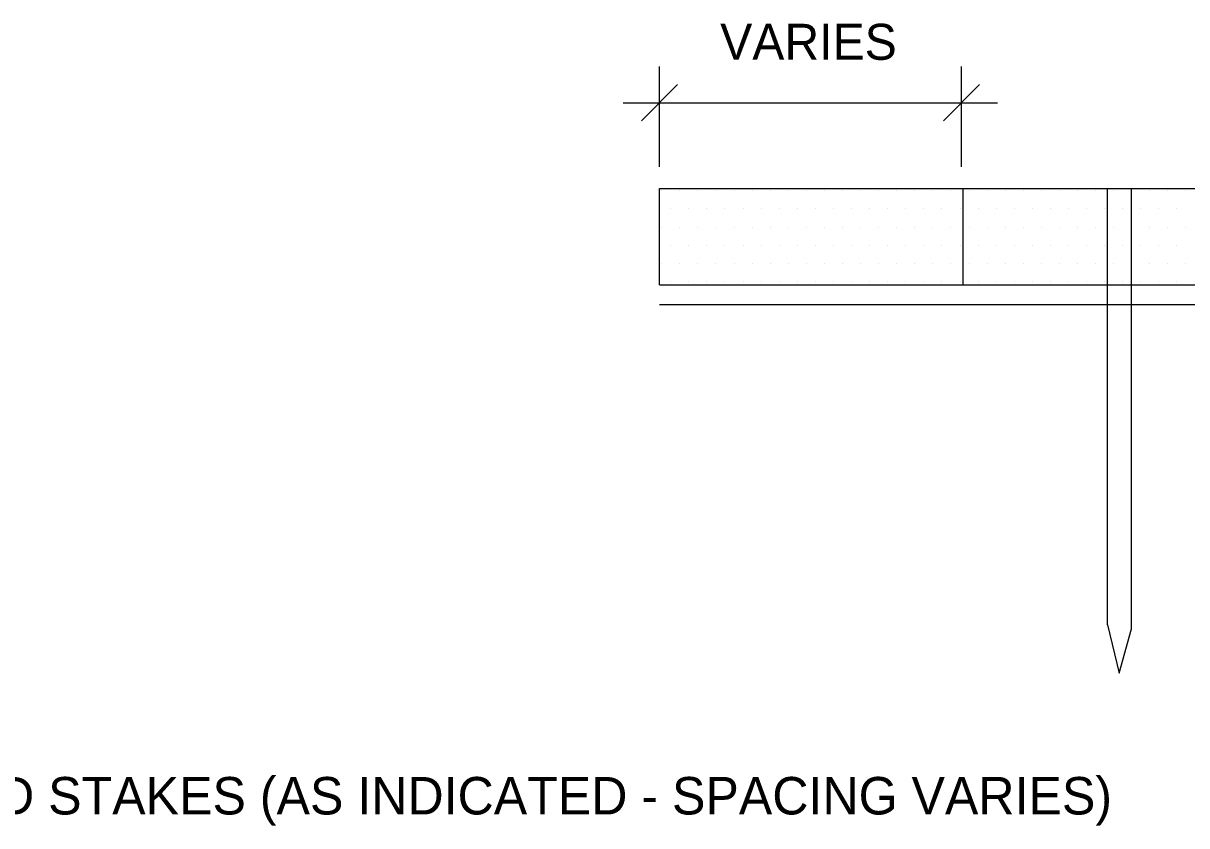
# Model space of a CAD drawing. Extents: x 638850 to 644908, y 297188 to 298900.
# Drawn here: x 641612.1 to 641700.1, y 297637.1 to 297697.8 of the extents above; entities that cross this region are included whole.
import ezdxf

# ---------------------------------------------------------------- set-up
doc = ezdxf.new("R2010")
doc.units = 0
for name, color, linetype in [('11', 7, 'Continuous'), ('3', 7, 'Continuous'), ('4', 7, 'Continuous'), ('5', 7, 'Continuous'), ('6', 7, 'Continuous'), ('7', 7, 'Continuous')]:
    doc.layers.add(name, color=color, linetype=linetype)

msp = doc.modelspace()

# ---------------------------------------------------------------- linework, layer by layer
at = {"layer": '11'}
for p, q in [((641660.41, 297685.127), (641660.41, 297685.127)), ((641661.777, 297685.127), (641661.777, 297685.127)), ((641663.143, 297685.127), (641663.143, 297685.127)), ((641664.51, 297685.127), (641664.51, 297685.127)), ((641665.877, 297685.127), (641665.877, 297685.127)), ((641667.244, 297685.127), (641667.244, 297685.127)), ((641668.611, 297685.127), (641668.611, 297685.127)), ((641669.978, 297685.127), (641669.978, 297685.127)), ((641671.345, 297685.127), (641671.345, 297685.127)), ((641672.712, 297685.127), (641672.712, 297685.127)), ((641674.078, 297685.127), (641674.078, 297685.127)), ((641675.445, 297685.127), (641675.445, 297685.127)), ((641676.812, 297685.127), (641676.812, 297685.127)), ((641678.179, 297685.127), (641678.179, 297685.127)), ((641679.546, 297685.127), (641679.546, 297685.127)), ((641680.913, 297685.127), (641680.913, 297685.127)), ((641682.28, 297685.127), (641682.28, 297685.127)), ((641683.647, 297685.127), (641683.647, 297685.127)), ((641685.013, 297685.127), (641685.013, 297685.127)), ((641686.38, 297685.127), (641686.38, 297685.127)), ((641687.747, 297685.127), (641687.747, 297685.127)), ((641689.114, 297685.127), (641689.114, 297685.127)), ((641690.481, 297685.127), (641690.481, 297685.127)), ((641691.848, 297685.127), (641691.848, 297685.127)), ((641693.215, 297685.127), (641693.215, 297685.127)), ((641694.582, 297685.127), (641694.582, 297685.127)), ((641695.948, 297685.127), (641695.948, 297685.127)), ((641697.315, 297685.127), (641697.315, 297685.127)), ((641698.682, 297685.127), (641698.682, 297685.127)), ((641700.049, 297685.127), (641700.049, 297685.127)), ((641661.094, 297683.76), (641661.094, 297683.76)), ((641662.459, 297683.76), (641662.459, 297683.76)), ((641663.828, 297683.76), (641663.828, 297683.76)), ((641665.193, 297683.76), (641665.193, 297683.76)), ((641666.562, 297683.76), (641666.562, 297683.76)), ((641667.926, 297683.76), (641667.926, 297683.76)), ((641669.295, 297683.76), (641669.295, 297683.76)), ((641670.66, 297683.76), (641670.66, 297683.76)), ((641672.029, 297683.76), (641672.029, 297683.76)), ((641673.394, 297683.76), (641673.394, 297683.76)), ((641674.763, 297683.76), (641674.763, 297683.76)), ((641676.128, 297683.76), (641676.128, 297683.76)), ((641677.497, 297683.76), (641677.497, 297683.76)), ((641678.861, 297683.76), (641678.861, 297683.76)), ((641680.23, 297683.76), (641680.23, 297683.76)), ((641681.595, 297683.76), (641681.595, 297683.76)), ((641682.964, 297683.76), (641682.964, 297683.76)), ((641684.329, 297683.76), (641684.329, 297683.76)), ((641685.698, 297683.76), (641685.698, 297683.76)), ((641687.063, 297683.76), (641687.063, 297683.76)), ((641688.432, 297683.76), (641688.432, 297683.76)), ((641689.796, 297683.76), (641689.796, 297683.76)), ((641691.165, 297683.76), (641691.165, 297683.76)), ((641692.53, 297683.76), (641692.53, 297683.76)), ((641693.899, 297683.76), (641693.899, 297683.76)), ((641695.264, 297683.76), (641695.264, 297683.76)), ((641696.633, 297683.76), (641696.633, 297683.76)), ((641697.998, 297683.76), (641697.998, 297683.76)), ((641699.367, 297683.76), (641699.367, 297683.76)), ((641660.41, 297682.393), (641660.41, 297682.393)), ((641661.777, 297682.393), (641661.777, 297682.393)), ((641663.143, 297682.393), (641663.143, 297682.393)), ((641664.51, 297682.393), (641664.51, 297682.393)), ((641665.877, 297682.393), (641665.877, 297682.393)), ((641667.244, 297682.393), (641667.244, 297682.393)), ((641668.611, 297682.393), (641668.611, 297682.393)), ((641669.978, 297682.393), (641669.978, 297682.393)), ((641671.345, 297682.393), (641671.345, 297682.393)), ((641672.712, 297682.393), (641672.712, 297682.393)), ((641674.078, 297682.393), (641674.078, 297682.393)), ((641675.445, 297682.393), (641675.445, 297682.393)), ((641676.812, 297682.393), (641676.812, 297682.393)), ((641678.179, 297682.393), (641678.179, 297682.393)), ((641679.546, 297682.393), (641679.546, 297682.393)), ((641680.913, 297682.393), (641680.913, 297682.393)), ((641682.28, 297682.393), (641682.28, 297682.393)), ((641683.647, 297682.393), (641683.647, 297682.393)), ((641685.013, 297682.393), (641685.013, 297682.393)), ((641686.38, 297682.393), (641686.38, 297682.393)), ((641687.747, 297682.393), (641687.747, 297682.393)), ((641689.114, 297682.393), (641689.114, 297682.393)), ((641690.481, 297682.393), (641690.481, 297682.393)), ((641691.848, 297682.393), (641691.848, 297682.393)), ((641693.215, 297682.393), (641693.215, 297682.393)), ((641694.582, 297682.393), (641694.582, 297682.393)), ((641695.948, 297682.393), (641695.948, 297682.393)), ((641697.315, 297682.393), (641697.315, 297682.393)), ((641698.682, 297682.393), (641698.682, 297682.393)), ((641700.049, 297682.393), (641700.049, 297682.393)), ((641661.094, 297681.026), (641661.094, 297681.026)), ((641662.459, 297681.026), (641662.459, 297681.026)), ((641663.828, 297681.026), (641663.828, 297681.026)), ((641665.193, 297681.026), (641665.193, 297681.026)), ((641666.562, 297681.026), (641666.562, 297681.026)), ((641667.926, 297681.026), (641667.926, 297681.026)), ((641669.295, 297681.026), (641669.295, 297681.026)), ((641670.66, 297681.026), (641670.66, 297681.026)), ((641672.029, 297681.026), (641672.029, 297681.026)), ((641673.394, 297681.026), (641673.394, 297681.026)), ((641674.763, 297681.026), (641674.763, 297681.026)), ((641676.128, 297681.026), (641676.128, 297681.026)), ((641677.497, 297681.026), (641677.497, 297681.026)), ((641678.861, 297681.026), (641678.861, 297681.026)), ((641680.23, 297681.026), (641680.23, 297681.026)), ((641681.595, 297681.026), (641681.595, 297681.026)), ((641682.964, 297681.026), (641682.964, 297681.026)), ((641684.329, 297681.026), (641684.329, 297681.026)), ((641685.698, 297681.026), (641685.698, 297681.026)), ((641687.063, 297681.026), (641687.063, 297681.026)), ((641688.432, 297681.026), (641688.432, 297681.026)), ((641689.796, 297681.026), (641689.796, 297681.026)), ((641691.165, 297681.026), (641691.165, 297681.026)), ((641692.53, 297681.026), (641692.53, 297681.026)), ((641693.899, 297681.026), (641693.899, 297681.026)), ((641695.264, 297681.026), (641695.264, 297681.026)), ((641696.633, 297681.026), (641696.633, 297681.026)), ((641697.998, 297681.026), (641697.998, 297681.026)), ((641699.367, 297681.026), (641699.367, 297681.026)), ((641660.41, 297679.659), (641660.41, 297679.659)), ((641661.777, 297679.659), (641661.777, 297679.659)), ((641663.143, 297679.659), (641663.143, 297679.659)), ((641664.51, 297679.659), (641664.51, 297679.659)), ((641665.877, 297679.659), (641665.877, 297679.659)), ((641667.244, 297679.659), (641667.244, 297679.659)), ((641668.611, 297679.659), (641668.611, 297679.659)), ((641669.978, 297679.659), (641669.978, 297679.659)), ((641671.345, 297679.659), (641671.345, 297679.659)), ((641672.712, 297679.659), (641672.712, 297679.659)), ((641674.078, 297679.659), (641674.078, 297679.659)), ((641675.445, 297679.659), (641675.445, 297679.659)), ((641676.812, 297679.659), (641676.812, 297679.659)), ((641678.179, 297679.659), (641678.179, 297679.659)), ((641679.546, 297679.659), (641679.546, 297679.659)), ((641680.913, 297679.659), (641680.913, 297679.659)), ((641682.28, 297679.659), (641682.28, 297679.659)), ((641683.647, 297679.659), (641683.647, 297679.659)), ((641685.013, 297679.659), (641685.013, 297679.659)), ((641686.38, 297679.659), (641686.38, 297679.659)), ((641687.747, 297679.659), (641687.747, 297679.659)), ((641689.114, 297679.659), (641689.114, 297679.659)), ((641690.481, 297679.659), (641690.481, 297679.659)), ((641691.848, 297679.659), (641691.848, 297679.659)), ((641693.215, 297679.659), (641693.215, 297679.659)), ((641694.582, 297679.659), (641694.582, 297679.659)), ((641695.948, 297679.659), (641695.948, 297679.659)), ((641697.315, 297679.659), (641697.315, 297679.659)), ((641698.682, 297679.659), (641698.682, 297679.659)), ((641700.049, 297679.659), (641700.049, 297679.659)), ((641661.094, 297678.292), (641661.094, 297678.292)), ((641662.459, 297678.292), (641662.459, 297678.292)), ((641663.828, 297678.292), (641663.828, 297678.292)), ((641665.193, 297678.292), (641665.193, 297678.292)), ((641666.562, 297678.292), (641666.562, 297678.292)), ((641667.926, 297678.292), (641667.926, 297678.292)), ((641669.295, 297678.292), (641669.295, 297678.292)), ((641670.66, 297678.292), (641670.66, 297678.292)), ((641672.029, 297678.292), (641672.029, 297678.292)), ((641673.394, 297678.292), (641673.394, 297678.292)), ((641674.763, 297678.292), (641674.763, 297678.292)), ((641676.128, 297678.292), (641676.128, 297678.292)), ((641677.497, 297678.292), (641677.497, 297678.292)), ((641678.861, 297678.292), (641678.861, 297678.292)), ((641680.23, 297678.292), (641680.23, 297678.292)), ((641681.595, 297678.292), (641681.595, 297678.292)), ((641682.964, 297678.292), (641682.964, 297678.292)), ((641684.329, 297678.292), (641684.329, 297678.292)), ((641685.698, 297678.292), (641685.698, 297678.292)), ((641687.063, 297678.292), (641687.063, 297678.292)), ((641688.432, 297678.292), (641688.432, 297678.292)), ((641689.796, 297678.292), (641689.796, 297678.292)), ((641691.165, 297678.292), (641691.165, 297678.292)), ((641692.53, 297678.292), (641692.53, 297678.292)), ((641693.899, 297678.292), (641693.899, 297678.292)), ((641695.264, 297678.292), (641695.264, 297678.292)), ((641696.633, 297678.292), (641696.633, 297678.292)), ((641697.998, 297678.292), (641697.998, 297678.292)), ((641699.367, 297678.292), (641699.367, 297678.292))]:
    msp.add_line(p, q, dxfattribs=at)
at = {"layer": '4'}
for p, q in [((641660.237, 297678.028), (641660.237, 297685.317)), ((641660.237, 297685.317), (641843.945, 297685.317)), ((641683.2, 297678.028), (641683.2, 297685.317)), ((641660.237, 297678.028), (641843.945, 297678.028))]:
    msp.add_line(p, q, dxfattribs=at)
at = {"layer": '5'}
for p, q in [((641660.237, 297686.959), (641660.237, 297694.528)), ((641683.076, 297686.959), (641683.076, 297694.528)), ((641658.87, 297690.428), (641661.604, 297693.162)), ((641681.709, 297690.428), (641684.443, 297693.162)), ((641657.503, 297691.795), (641685.809, 297691.795)), ((641683.076, 297691.795), (641683.076, 297691.795))]:
    msp.add_line(p, q, dxfattribs=at)
at = {"layer": '6'}
for p, q in [((641694.127, 297652.315), (641694.127, 297685.308)), ((641694.127, 297685.308), (641695.918, 297685.308)), ((641695.918, 297652.002), (641695.918, 297685.308)), ((641694.127, 297652.315), (641694.999, 297648.658)), ((641694.999, 297648.658), (641695.918, 297652.002))]:
    msp.add_line(p, q, dxfattribs=at)
at = {"layer": '7'}
msp.add_line((641660.237, 297676.545), (641843.945, 297676.545), dxfattribs=at)

# ---------------------------------------------------------------- texts
at = {"layer": '3'}
for s, height, p in [('VARIES', 2.7228, (641664.828, 297695.041)), ('WOOD STAKES (AS INDICATED - SPACING VARIES)', 2.83405, (641600.754, 297637.97))]:
    msp.add_text(s, height=height, dxfattribs=at).set_placement(p)

doc.saveas('drawing.dxf')
